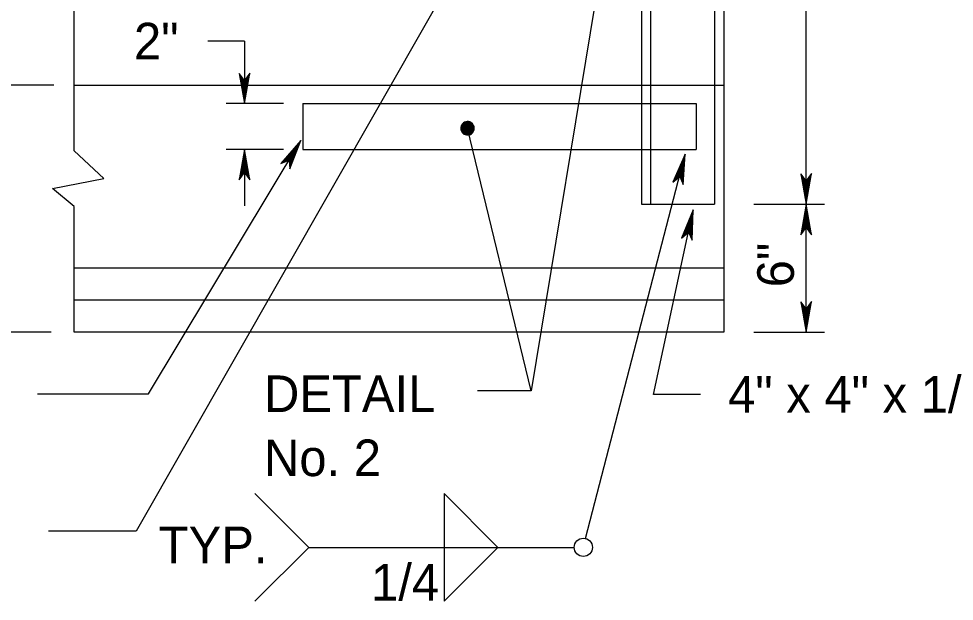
# Model space of a CAD drawing. Extents: x 499866 to 500993, y 499985 to 500645.
# Drawn here: x 500302.2 to 500404.4, y 500468.8 to 500532.5 of the extents above; entities that cross this region are included whole.
import ezdxf

# ---------------------------------------------------------------- set-up
doc = ezdxf.new("R2010")
doc.units = 0
doc.layers.add('24', color=7, linetype='Continuous')
doc.layers.add('5', color=7, linetype='Continuous')

msp = doc.modelspace()

# ---------------------------------------------------------------- linework, layer by layer
at = {"layer": '24'}
for points in [[(500357.7, 500551.31), (500315.02, 500476.51), (500305.43, 500476.51)], [(500365.7, 500537.61), (500358.16, 500491.83), (500352.28, 500491.83)], [(500326.85, 500523.22), (500327.44, 500526.54), (500326.85, 500525.75), (500326.27, 500526.52), (500326.85, 500523.22), (500326.85, 500523.44), (500327.4, 500526.45), (500326.85, 500525.69), (500326.32, 500526.39), (500326.84, 500523.56), (500326.85, 500523.67), (500327.31, 500526.25), (500326.85, 500525.67), (500326.39, 500526.26), (500326.85, 500523.72), (500326.84, 500523.83), (500327.24, 500526.08), (500326.85, 500525.64), (500326.45, 500526.09), (500326.84, 500524.15), (500326.84, 500524.34), (500327.16, 500525.92), (500326.86, 500525.61), (500326.53, 500525.94), (500326.85, 500524.37), (500326.86, 500524.55), (500327.07, 500525.74), (500326.84, 500525.51), (500326.61, 500525.75), (500326.85, 500524.71), (500326.87, 500524.88), (500327.01, 500525.59), (500326.85, 500525.47), (500326.67, 500525.67), (500326.85, 500524.97), (500326.96, 500525.43), (500326.84, 500525.36), (500326.71, 500525.57), (500326.84, 500525.08), (500326.91, 500525.39), (500326.81, 500525.26), (500326.75, 500525.41), (500326.85, 500525.26), (500326.86, 500525.34)], [(500358.16, 500491.83), (500351.2, 500520.53)], [(500333, 500519.18), (500330.82, 500516.67), (500331.72, 500517.04), (500331.81, 500516.09), (500333, 500519.18), (500332.89, 500518.99), (500330.9, 500516.73), (500331.75, 500517.09), (500331.84, 500516.23), (500332.84, 500518.88), (500332.77, 500518.8), (500331.07, 500516.85), (500331.76, 500517.11), (500331.84, 500516.37), (500332.74, 500518.75), (500332.7, 500518.65), (500331.22, 500516.96), (500331.77, 500517.13), (500331.88, 500516.54), (500332.54, 500518.38), (500332.44, 500518.22), (500331.37, 500517.06), (500331.78, 500517.16), (500331.89, 500516.72), (500332.41, 500518.2), (500332.31, 500518.06), (500331.54, 500517.16), (500331.85, 500517.24), (500331.92, 500516.91), (500332.24, 500517.92), (500332.14, 500517.78), (500331.66, 500517.25), (500331.86, 500517.27), (500331.91, 500517.01), (500332.11, 500517.7), (500331.78, 500517.37), (500331.92, 500517.36), (500331.93, 500517.12), (500332.07, 500517.59), (500331.85, 500517.38), (500332, 500517.43), (500331.97, 500517.28), (500331.97, 500517.45), (500331.92, 500517.39)], [(500326.85, 500518.22), (500326.26, 500514.9), (500326.85, 500515.69), (500327.43, 500514.91), (500326.85, 500518.22), (500326.86, 500518), (500326.31, 500514.99), (500326.86, 500515.75), (500327.38, 500515.05), (500326.87, 500517.88), (500326.85, 500517.77), (500326.39, 500515.19), (500326.86, 500515.77), (500327.31, 500515.18), (500326.85, 500517.72), (500326.87, 500517.61), (500326.46, 500515.36), (500326.85, 500515.79), (500327.26, 500515.35), (500326.87, 500517.29), (500326.87, 500517.1), (500326.55, 500515.52), (500326.84, 500515.83), (500327.17, 500515.5), (500326.85, 500517.07), (500326.84, 500516.89), (500326.64, 500515.7), (500326.87, 500515.93), (500327.1, 500515.68), (500326.85, 500516.73), (500326.84, 500516.56), (500326.7, 500515.85), (500326.86, 500515.96), (500327.04, 500515.77), (500326.85, 500516.47), (500326.74, 500516.01), (500326.87, 500516.08), (500327, 500515.87), (500326.87, 500516.36), (500326.79, 500516.05), (500326.89, 500516.18), (500326.95, 500516.03), (500326.86, 500516.18), (500326.84, 500516.1)], [(500374.97, 500517.69), (500373.65, 500514.64), (500374.4, 500515.27), (500374.78, 500514.39), (500374.97, 500517.69), (500374.92, 500517.48), (500373.72, 500514.72), (500374.42, 500515.33), (500374.76, 500514.53), (500374.91, 500517.37), (500374.87, 500517.26), (500373.85, 500514.89), (500374.42, 500515.34), (500374.72, 500514.67), (500374.85, 500517.21), (500374.85, 500517.1), (500373.95, 500515.04), (500374.42, 500515.37), (500374.71, 500514.85), (500374.77, 500516.8), (500374.73, 500516.62), (500374.07, 500515.18), (500374.42, 500515.4), (500374.66, 500515.01), (500374.71, 500516.59), (500374.66, 500516.42), (500374.2, 500515.33), (500374.47, 500515.5), (500374.63, 500515.21), (500374.63, 500516.26), (500374.58, 500516.11), (500374.29, 500515.45), (500374.47, 500515.53), (500374.59, 500515.3), (500374.57, 500516.02), (500374.36, 500515.6), (500374.5, 500515.63), (500374.58, 500515.41), (500374.56, 500515.9), (500374.42, 500515.63), (500374.55, 500515.73), (500374.57, 500515.57), (500374.51, 500515.73), (500374.48, 500515.66)], [(500374.97, 500517.69), (500373.65, 500514.64), (500374.4, 500515.27), (500374.78, 500514.39), (500374.97, 500517.69), (500374.92, 500517.48), (500373.72, 500514.72), (500374.42, 500515.33), (500374.76, 500514.53), (500374.91, 500517.37), (500374.87, 500517.26), (500373.85, 500514.89), (500374.42, 500515.34), (500374.72, 500514.67), (500374.85, 500517.21), (500374.85, 500517.1), (500373.95, 500515.04), (500374.42, 500515.37), (500374.71, 500514.85), (500374.77, 500516.8), (500374.73, 500516.62), (500374.07, 500515.18), (500374.42, 500515.4), (500374.66, 500515.01), (500374.71, 500516.59), (500374.66, 500516.42), (500374.2, 500515.33), (500374.47, 500515.5), (500374.63, 500515.21), (500374.63, 500516.26), (500374.58, 500516.11), (500374.29, 500515.45), (500374.47, 500515.53), (500374.59, 500515.3), (500374.57, 500516.02), (500374.36, 500515.6), (500374.5, 500515.63), (500374.58, 500515.41), (500374.56, 500515.9), (500374.42, 500515.63), (500374.55, 500515.73), (500374.57, 500515.57), (500374.51, 500515.73), (500374.48, 500515.66)], [(500388.19, 500512.23), (500388.78, 500515.58), (500388.19, 500514.78), (500387.61, 500515.56), (500388.19, 500512.23), (500388.19, 500512.45), (500388.74, 500515.48), (500388.19, 500514.71), (500387.66, 500515.42), (500388.18, 500512.57), (500388.19, 500512.68), (500388.65, 500515.28), (500388.19, 500514.7), (500387.73, 500515.3), (500388.19, 500512.73), (500388.18, 500512.84), (500388.59, 500515.11), (500388.19, 500514.67), (500387.78, 500515.12), (500388.18, 500513.17), (500388.18, 500513.35), (500388.5, 500514.95), (500388.2, 500514.64), (500387.87, 500514.97), (500388.19, 500513.39), (500388.2, 500513.57), (500388.41, 500514.76), (500388.18, 500514.53), (500387.95, 500514.78), (500388.19, 500513.73), (500388.21, 500513.9), (500388.35, 500514.62), (500388.19, 500514.5), (500388.01, 500514.7), (500388.19, 500513.99), (500388.3, 500514.46), (500388.18, 500514.39), (500388.05, 500514.59), (500388.18, 500514.11), (500388.25, 500514.41), (500388.15, 500514.28), (500388.09, 500514.43), (500388.19, 500514.29), (500388.2, 500514.36)], [(500388.19, 500512.23), (500387.6, 500508.88), (500388.19, 500509.68), (500388.78, 500508.89), (500388.19, 500512.23), (500388.2, 500512), (500387.64, 500508.97), (500388.2, 500509.74), (500388.73, 500509.03), (500388.21, 500511.88), (500388.19, 500511.77), (500387.73, 500509.17), (500388.2, 500509.76), (500388.65, 500509.16), (500388.19, 500511.72), (500388.21, 500511.61), (500387.8, 500509.34), (500388.19, 500509.78), (500388.6, 500509.33), (500388.21, 500511.29), (500388.21, 500511.1), (500387.88, 500509.51), (500388.18, 500509.82), (500388.52, 500509.48), (500388.19, 500511.06), (500388.18, 500510.88), (500387.98, 500509.69), (500388.21, 500509.92), (500388.44, 500509.67), (500388.19, 500510.72), (500388.18, 500510.55), (500388.04, 500509.83), (500388.2, 500509.95), (500388.38, 500509.76), (500388.19, 500510.46), (500388.08, 500510), (500388.21, 500510.06), (500388.34, 500509.86), (500388.21, 500510.35), (500388.13, 500510.04), (500388.23, 500510.17), (500388.29, 500510.02), (500388.2, 500510.17), (500388.18, 500510.09)], [(500375.85, 500511.61), (500374.6, 500508.52), (500375.33, 500509.17), (500375.73, 500508.3), (500375.85, 500511.61), (500375.81, 500511.39), (500374.66, 500508.61), (500375.35, 500509.23), (500375.71, 500508.44), (500375.8, 500511.27), (500375.76, 500511.17), (500374.79, 500508.78), (500375.35, 500509.24), (500375.66, 500508.58), (500375.75, 500511.12), (500375.74, 500511.01), (500374.88, 500508.93), (500375.35, 500509.27), (500375.65, 500508.75), (500375.67, 500510.7), (500375.64, 500510.52), (500375, 500509.07), (500375.35, 500509.3), (500375.6, 500508.92), (500375.61, 500510.49), (500375.57, 500510.33), (500375.13, 500509.22), (500375.4, 500509.4), (500375.56, 500509.11), (500375.54, 500510.17), (500375.49, 500510.01), (500375.21, 500509.35), (500375.39, 500509.43), (500375.52, 500509.21), (500375.49, 500509.92), (500375.29, 500509.5), (500375.42, 500509.54), (500375.51, 500509.31), (500375.48, 500509.81), (500375.35, 500509.53), (500375.47, 500509.63), (500375.5, 500509.48), (500375.44, 500509.64), (500375.4, 500509.57)], [(500388.19, 500498.24), (500388.78, 500501.59), (500388.19, 500500.79), (500387.61, 500501.57), (500388.19, 500498.24), (500388.19, 500498.46), (500388.74, 500501.49), (500388.19, 500500.72), (500387.66, 500501.43), (500388.18, 500498.58), (500388.19, 500498.69), (500388.65, 500501.29), (500388.19, 500500.71), (500387.73, 500501.31), (500388.19, 500498.74), (500388.18, 500498.85), (500388.59, 500501.12), (500388.19, 500500.68), (500387.78, 500501.13), (500388.18, 500499.18), (500388.18, 500499.37), (500388.5, 500500.96), (500388.2, 500500.65), (500387.87, 500500.98), (500388.19, 500499.4), (500388.2, 500499.58), (500388.41, 500500.77), (500388.18, 500500.54), (500387.95, 500500.79), (500388.19, 500499.74), (500388.21, 500499.91), (500388.35, 500500.63), (500388.19, 500500.51), (500388.01, 500500.71), (500388.19, 500500), (500388.3, 500500.47), (500388.18, 500500.4), (500388.05, 500500.61), (500388.18, 500500.12), (500388.25, 500500.42), (500388.15, 500500.3), (500388.09, 500500.44), (500388.19, 500500.3), (500388.2, 500500.37)]]:
    msp.add_lwpolyline(points, dxfattribs=at)
for radius, start, end in [(0.738, 103.6184, 283.6184), (0.714, 103.6184, 283.6184), (0.689, 103.6184, 283.6184), (0.664, 103.6184, 283.6184), (0.64, 103.6184, 283.6184), (0.615, 103.6184, 283.6184), (0.591, 103.6184, 283.6184), (0.566, 103.6184, 283.6184), (0.738, 283.6184, 103.6184), (0.714, 283.6184, 103.6184), (0.689, 283.6184, 103.6184), (0.664, 283.6184, 103.6184), (0.64, 283.6184, 103.6184), (0.615, 283.6184, 103.6184), (0.591, 283.6184, 103.6184), (0.566, 283.6184, 103.6184), (0.541, 103.6184, 283.6184), (0.517, 103.6184, 283.6184), (0.492, 103.6184, 283.6184), (0.468, 103.6184, 283.6184), (0.443, 103.6184, 283.6184), (0.418, 103.6184, 283.6184), (0.394, 103.6184, 283.6184), (0.369, 103.6184, 283.6184), (0.344, 103.6184, 283.6184), (0.32, 103.6184, 283.6184), (0.295, 103.6184, 283.6184), (0.271, 103.6184, 283.6184), (0.246, 103.6184, 283.6184), (0.221, 103.6184, 283.6184), (0.197, 103.6184, 283.6184), (0.172, 103.6184, 283.6184), (0.148, 103.6184, 283.6184), (0.541, 283.6184, 103.6184), (0.517, 283.6184, 103.6184), (0.123, 103.6184, 283.6184), (0.492, 283.6184, 103.6184), (0.468, 283.6184, 103.6184), (0.443, 283.6184, 103.6184), (0.418, 283.6184, 103.6184), (0.0984, 103.6184, 283.6184), (0.394, 283.6184, 103.6184), (0.369, 283.6184, 103.6184), (0.344, 283.6184, 103.6184), (0.32, 283.6184, 103.6184), (0.295, 283.6184, 103.6184), (0.0738, 103.6184, 283.6184), (0.271, 283.6184, 103.6184), (0.246, 283.6184, 103.6184), (0.221, 283.6184, 103.6184), (0.197, 283.6184, 103.6184), (0.0492, 103.6184, 283.6184), (0.172, 283.6184, 103.6184), (0.148, 283.6184, 103.6184), (0.123, 283.6184, 103.6184), (0.0984, 283.6184, 103.6184), (0.0738, 283.6184, 103.6184), (0.0246, 103.6184, 283.6184), (0.0492, 283.6184, 103.6184), (0.0246, 283.6184, 103.6184)]:
    msp.add_arc((500351.2, 500520.53), radius, start, end, dxfattribs=at)
at = {"layer": '5'}
for p, q in [((500370.21, 500563.19), (500370.21, 500512.23)), ((500371.21, 500563.19), (500371.21, 500512.23)), ((500378.2, 500563.19), (500378.2, 500512.23)), ((500379.2, 500563.19), (500379.2, 500498.24)), ((500388.19, 500512.23), (500388.19, 500563.19)), ((500308.25, 500518.07), (500308.25, 500542.36)), ((500326.85, 500530.05), (500322.82, 500530.05)), ((500326.85, 500530.05), (500326.85, 500523.22)), ((500306, 500525.22), (500294.34, 500525.22)), ((500308.25, 500525.22), (500379.2, 500525.22)), ((500331.09, 500523.22), (500324.85, 500523.22)), ((500333.23, 500523.22), (500376.2, 500523.22)), ((500333.23, 500523.22), (500333.23, 500518.22)), ((500376.2, 500523.22), (500376.2, 500518.22)), ((500308.25, 500518.07), (500311.47, 500515.03)), ((500331.09, 500518.22), (500324.85, 500518.22)), ((500326.85, 500518.22), (500326.85, 500512.07)), ((500333.23, 500518.22), (500376.2, 500518.22)), ((500364.11, 500475.7), (500374.97, 500517.69)), ((500305.86, 500513.93), (500311.47, 500515.03)), ((500308.25, 500511.99), (500305.86, 500513.93)), ((500308.25, 500498.24), (500308.25, 500511.99)), ((500370.21, 500512.23), (500378.2, 500512.23)), ((500382.5, 500512.23), (500390.19, 500512.23)), ((500388.19, 500498.24), (500388.19, 500512.23)), ((500379.2, 500505.23), (500308.25, 500505.23)), ((500379.2, 500501.73), (500308.25, 500501.73)), ((500305.74, 500498.24), (500294.34, 500498.24)), ((500379.2, 500498.24), (500308.25, 500498.24)), ((500382.5, 500498.24), (500390.19, 500498.24)), ((500327.99, 500480.63), (500333.88, 500474.74)), ((500348.64, 500480.63), (500354.53, 500474.74)), ((500348.64, 500480.63), (500348.64, 500468.85)), ((500333.88, 500474.74), (500327.99, 500468.85)), ((500333.88, 500474.74), (500354.53, 500474.74)), ((500354.53, 500474.74), (500348.64, 500468.85)), ((500354.53, 500474.74), (500362.86, 500474.74))]:
    msp.add_line(p, q, dxfattribs=at)
for points in [[(500304.22, 500491.53), (500316.37, 500491.53), (500333, 500519.18)], [(500376.67, 500491.45), (500371.54, 500491.45), (500375.85, 500511.61)]]:
    msp.add_lwpolyline(points, dxfattribs=at)
msp.add_circle((500363.86, 500474.74), 0.999, dxfattribs=at)

# ---------------------------------------------------------------- texts
for s, p in [('2"', (500314.77, 500528.05)), ('DETAIL', (500328.97, 500489.52)), ('4" x 4" x 1/2" TUBE', (500379.67, 500489.45)), ('No. 2', (500328.97, 500482.52)), ('TYP.', (500317.47, 500473.01)), ('1/4', (500340.67, 500468.93))]:
    msp.add_text(s, height=4, dxfattribs=at).set_placement(p)
msp.add_text('6"', height=4, rotation=90, dxfattribs=at).set_placement((500386.86, 500503.15))

doc.saveas('drawing.dxf')
